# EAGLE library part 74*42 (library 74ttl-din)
4-line to 10-line DECODER (1-of-10)
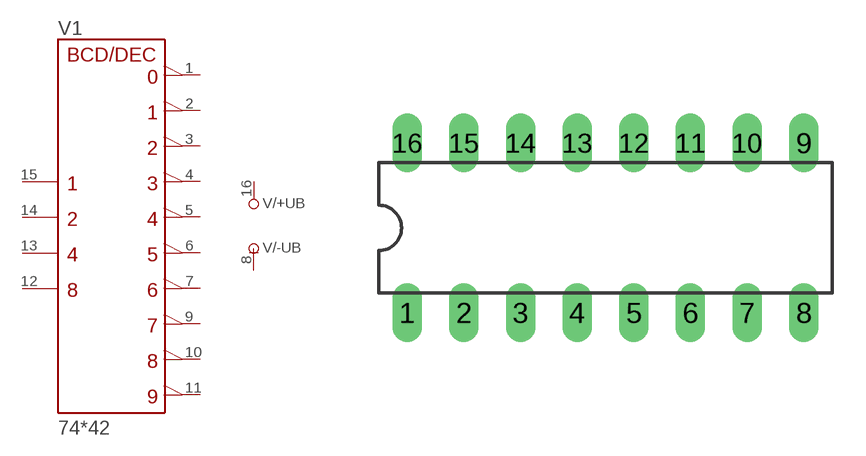
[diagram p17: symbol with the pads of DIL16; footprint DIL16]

Designator prefix V; gates /+UB=+UB /-UB=-UB 1=42

## 7442N  [DIL16]
1  1:Y0  out
2  1:Y1  out
3  1:Y2  out
4  1:Y3  out
5  1:Y4  out
6  1:Y5  out
7  1:Y6  out
8  /-UB:-UB  pwr
9  1:Y7  out
10  1:Y8  out
11  1:Y9  out
12  1:D  in
13  1:C  in
14  1:B  in
15  1:A  in
16  /+UB:+UB  pwr

## Footprint DIL16 (pad centres in mm)
Dual In Line Package
drill 0.813 long: 1 -8.89,-3.81; 2 -6.35,-3.81; 3 -3.81,-3.81; 4 -1.27,-3.81; 5 1.27,-3.81; 6 3.81,-3.81; 7 6.35,-3.81; 8 8.89,-3.81; 9 8.89,3.81; 10 6.35,3.81; 11 3.81,3.81; 12 1.27,3.81; 13 -1.27,3.81; 14 -3.81,3.81; 15 -6.35,3.81; 16 -8.89,3.81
